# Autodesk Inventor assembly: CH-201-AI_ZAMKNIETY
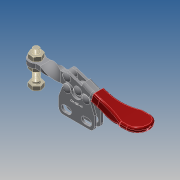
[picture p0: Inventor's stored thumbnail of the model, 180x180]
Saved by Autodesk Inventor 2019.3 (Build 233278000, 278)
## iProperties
Company: Î¢ÈíÖÐ¹ú
Created: 2012-09
Part Number: CH-201-AI_ZAMKNIETY
Material: Ogólny
Description: STEP AP203
Document SubType Name: Assembly
Designer: CADENGINEERING4
Sending System: SolidWorks 2010
Preprocessor: SwSTEP 2.0
Title: CH-201-AI.STEP
Author: Î¢ÈíÓÃ»§
Revision Number: ÈÎºÎ
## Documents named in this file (8)
- E:\STRONA\Horizontal toggle clamp\CH-201-AI\CH-201-AI_ZAMKNIETY.iam
- E:\STRONA\Horizontal toggle clamp\CH-201-AI\CH-201-A-04.ipt
- E:\STRONA\Horizontal toggle clamp\CH-201-AI\CH-201-A-02 SOLID BAR.ipt
- E:\STRONA\Horizontal toggle clamp\CH-201-AI\CH-SA-042007 SPINDLE SUPPLIED.ipt
- E:\STRONA\Horizontal toggle clamp\CH-201-AI\CH-201-A-06.ipt
- E:\STRONA\Horizontal toggle clamp\CH-201-AI\CH-201-03 HANDLE.iam
- E:\STRONA\Horizontal toggle clamp\CH-201-AI\M4 Nut.ipt
- E:\STRONA\Horizontal toggle clamp\CH-201-AI\CH-201-AI-01 FLANGED BASE.ipt
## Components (12 placed, 12 different names)
1. CH-201-A-04_1
2. CH-201-A-02 SOLID BAR_2
3. CH-SA-042007 SPINDLE SUPPLIED_3
4. CH-201-A-06_4
5. CH-201-A-04_5
6. CH-201-03 HANDLE_6 [sub-assembly]
7. CH-201-A-06_7
8. CH-201-A-06_8
9. M4 Nut_9
10. M4 Nut_10
11. CH-201-AI-01 FLANGED BASE_11
12. CH-201-A-06_12
